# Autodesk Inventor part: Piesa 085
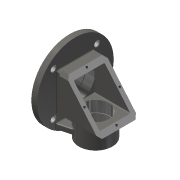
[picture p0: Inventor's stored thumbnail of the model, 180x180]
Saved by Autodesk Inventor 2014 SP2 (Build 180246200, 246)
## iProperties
Created: 2009-02
Part Number: Piesa 085
Document SubType Name: Modeling
Designer: Costel
Material: Steel, Cast
Density: 7.85 g/cm^3
Appearance: Steel - Cast
Mass: 4118.55 g
Surface Area: 1138.26 cm^2
Volume: 524.656 cm^3
Author: Costel
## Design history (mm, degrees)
sketch "Sketch2"
  geometry: L1 (0, -8.7)-(0, 113.1) reference; L2 (35.2, 0)-(-9.6, 0) reference; L3 (0, 87)-(13, 87); L4 (13, 87)-(13, 46); L5 (13, 46)-(17, 46); L6 (17, 46)-(32, 40.54); L7 (32, 40.54)-(32, 0); L8 (32, 0)-(0, 0); L9 (0, 0)-(0, 87)
  constraints: 14 end point, 4 point on line, 3 perpendicular, 2 parallel
  dimensions: "d1" = 174 diameter of L3 L2; "d2" = 92 diameter of L5 L2; "d3" = 20 deg angle of L5 L6; "d4" = 13 distance of L3.start L3.end; "d5" = 19 distance between parallel lines of L4 L7; "d6" = 4 distance of L4.end L5.end
revolve "Revolution1" sketch "Sketch2" stored, may be unused: angle "d7" = 90 deg
sketch "Sketch3"
  geometry: L1 (104.4, 0)-(-139.2, 0) reference; L2 (0, -104.4)-(0, 139.2) reference; L3 (-42.5, -42.5)-(42.5, -42.5); L4 (42.5, -42.5)-(42.5, 42.5); L5 (42.5, 42.5)-(-42.5, 42.5); L6 (-42.5, 42.5)-(-42.5, -42.5)
  constraints: 8 end point, 2 parallel, 2 perpendicular, 1 horizontal, 2 other
  dimensions: "d8" = 85 distance of L5.end L3.start
extrude "Extrusion1" join sketch "Sketch3" distance "d9" = 8; taper "d10" = 0 deg
sketch "Sketch4"
  geometry: L1 (-38, -45)-(38, -45); L2 (45, -38)-(45, 38); L3 (38, 45)-(-38, 45); L4 (-45, 38)-(-45, -38); L5 (0, -104.4)-(0, 139.2) reference; L6 (104.4, 0)-(-139.2, 0) reference; L7 (-45, -38)-(-38, -45); L8 (38, -45)-(45, -38); L9 (45, 38)-(38, 45); L10 (-38, 45)-(-45, 38); 4 further points
  constraints: 16 end point, 8 point on line, 2 parallel, 2 perpendicular, 1 horizontal, 2 other
  dimensions: "d11" = 90 distance of point (-45, 45) point (-45, -45); "d12" = 7 distance of L4.end point (-45, -45); "d13" = 7 distance of L1.start point (-45, -45) (= d12); "d14" = 7 distance of L1.end point (45, -45) (= d12); "d15" = 7 distance of L2.start point (45, -45) (= d14); "d16" = 7 distance of L2.end point (45, 45) (= d12); "d17" = 7 distance of L3.start point (45, 45) (= d16); "d18" = 7 distance of L3.end point (-45, 45) (= d12); "d19" = 7 distance of L4.start point (-45, 45) (= d18)
extrude "Extrusion2" join sketch "Sketch4" distance "d20" = 90.51897; taper "d21" = 0 deg
sketch "Sketch5"
  geometry: L1 (-45, -38)-(-45, 38) reference; L2 (-38, -45)-(-45, -38) reference; L3 (38, -45)-(-38, -45) reference; L4 (45, -38)-(38, -45) reference; L5 (45, 38)-(45, -38) reference; L6 (38, 45)-(45, 38) reference; L7 (-38, 45)-(38, 45) reference; L8 (-45, 38)-(-38, 45) reference; C1 r 87 at (0, 0) reference
extrude "Extrusion3" cut sketch "Sketch5" stored distance "d22" = 90.51897; taper "d23" = 0 deg
sketch "Sketch6"
  geometry: L1 (0, 7)-(90.519, 7) reference; L2 (-8, 49)-(-8, -125) reference; L3 (-53.052, -38)-(129.675, -38) reference; L4 (90.519, 0)-(90.519, 7) reference; L5 (0, -83)-(90.519, -83) reference; L6 (90.519, -83)-(90.519, -76) reference; L7 (90.519, -83)-(15, 7); L8 (15, 7)-(90.519, 7); L9 (90.519, 7)-(90.519, -83)
  constraints: 6 end point, 2 perpendicular, 1 point on line
  dimensions: "d24" = 23 distance from line of L2 L7.end
extrude "Extrusion4" cut sketch "Sketch6" distance "d25" = 90.51897; taper "d26" = 0 deg
sketch "Sketch7"
  geometry: L1 (0, -104.4)-(0, 139.2) reference; L2 (45.052, 0)-(-137.675, 0) reference; L3 (32, -40.54)-(32, 40.54) reference; L4 (13.65, 36)-(32, 36); L5 (32, 36)-(32, 0); L6 (11, 36)-(11, 37.5); L7 (11, 37.5)-(13.65, 37.5); L8 (13.65, 37.5)-(13.65, 36); L9 (32, 0)-(-8, 0); L10 (-8, 0)-(-8, 36); L11 (-8, 36)-(11, 36)
  constraints: 16 end point, 2 parallel, 1 collinear, 1 horizontal, 1 midpoint, 1 perpendicular
  dimensions: "d27" = 19 distance between parallel lines of L10 L6; "d28" = 2.65 distance of L6.end L7.end; "d29" = 40 distance between parallel lines of L10 L3; "d30" = 72 diameter of L4 L2; "d31" = 75 diameter of L7 L2
revolve "Revolution2" sketch "Sketch7" stored, may be unused: angle "d32" = 90 deg
sketch "Sketch8"
  geometry: L1 (-104.4, 0)-(139.2, 0) reference; L2 (35, 35)-(-35, 35); L3 (-35, 35)-(-35, -35); L4 (-35, -35)-(35, -35); L5 (35, -35)-(35, 35); L6 (0, -104.4)-(0, 139.2) reference
  constraints: 8 end point, 2 parallel, 2 perpendicular, 1 horizontal, 2 other
  dimensions: "d33" = 70 distance of L4.end L2.start
extrude "Extrusion5" cut sketch "Sketch8" stored distance "d34" = 90.51897; taper "d35" = 0 deg
fillet "Fillet3" dims "d102" = 2
fillet "Fillet4" dims "d103" = 2
sketch "Sketch9"
  geometry: L1 (45.052, 0)-(-137.675, 0) reference; L2 (0, -104.4)-(0, 139.2) reference; L3 (-46, 0)-(-46, -86); L4 (-8, -45)-(-98.519, -45) reference; L5 (-46, -86)-(-84, -86); L6 (-84, -86)-(-84, -45); L7 (-84, -45)-(-46, -45); L8 (-46, -45)-(-46, -86)
  constraints: 10 end point, 3 parallel, 2 point on line, 1 collinear, 1 horizontal, 1 perpendicular
  dimensions: "d36" = 46 distance between parallel lines of L2 L3; "d37" = 86 distance from line of L1 L3.end; "d38" = 76 diameter of L6 L3
revolve "Revolution3" sketch "Sketch9" stored, may be unused: angle "d39" = 90 deg
sketch "Sketch10"
  geometry: L1 (0, -118.76)-(0, 222.28) reference; L2 (63.325, 0)-(-192.493, 0) reference; L3 (-8, -35)-(-90.128, -35) reference; L4 (-8, -86)-(-84, -86) reference; L5 (-46, 0)-(-46, -86); L6 (-46, -86)-(-77, -86); L7 (-77, -35)-(-46, -35); L8 (-46, -35)-(-46, -86); L9 (-77, -58.7)-(-78.5, -58.7); L10 (-78.5, -58.7)-(-78.5, -60.85); L11 (-78.5, -60.85)-(-77, -60.85); L12 (-77, -78.85)-(-78.5, -78.85); L13 (-78.5, -78.85)-(-78.5, -81); L14 (-78.5, -81)-(-77, -81); L15 (-77, -58.7)-(-77, -35); L16 (-77, -86)-(-77, -81); L17 (-77, -78.85)-(-77, -60.85)
  constraints: 26 end point, 12 perpendicular, 6 parallel, 3 collinear, 2 point on line, 1 horizontal, 1 midpoint
  dimensions: "d58" = 62 diameter of L16 L5; "d59" = 65 diameter of L13 L5; "d60" = 2.15 distance of L12.end L13.end; "d61" = 2.15 distance of L9.end L10.end (= d60); "d62" = 5 distance of L6.end L14.end; "d63" = 18 distance of L12.start L11.end
revolve "Revolution4" sketch "Sketch10" stored, may be unused: angle "d64" = 90 deg
chamfer "Chamfer1" distance "d65" = 1; stored, may be unused: second distance "d66" = 2, angle "d67" = 45 deg
sketch "Sketch11"
  geometry: L1 (42.5, 40.5)-(42.5, -40.5) reference; L2 (42.5, -15)-(83, -15); L3 (83, -15)-(83, 15); L4 (83, 15)-(42.5, 15); L5 (42.5, 15)-(42.5, -15); L6 (104.4, 0)-(-139.2, 0) reference; C1 r 87 at (0, 0) reference
  constraints: 8 end point, 2 parallel, 1 horizontal, 1 perpendicular, 1 point on line, 1 other
  dimensions: "d69" = 83 distance from line of C1.centre L3; "d70" = 30 distance between parallel lines of L4 L2
extrude "Extrusion6" join sketch "Sketch11" stored distance "d71" = 90.51897; taper "d72" = 0 deg
sketch "Sketch12"
  geometry: L1 (0, 0)-(49.497, 49.497); L2 (-104.4, 0)-(139.2, 0) reference; C1 r 87 at (0, 0) reference; 1 further point
  constraints: 2 end point, 1 coincident
  dimensions: "d73" = 45 deg angle of L2 L1; "d74" = 70 distance of L1.start L1.end
hole "Hole1" sketch "Sketch12" at (49.497, 49.497) diameter "d75" = 11; stored, may be unused: countersink angle "d79" = 90 deg, drill point angle "d81" = 118 deg; dims "d76" = 6, "d77" = 25, "d78" = 5, "d80" = 8
fillet "Fillet1" dims "d85" = 2
chamfer "Chamfer2" distance "d86" = 1; stored, may be unused: second distance "d87" = 2, angle "d88" = 45 deg
pattern_circular "Circular Pattern2" dims "d90" = 360 deg
fillet "Fillet2" dims "d92" = 0.5
workplane "Work Plane1"
sketch "Sketch13"
  geometry: L1 (0, -45)-(33.726, -35.963); L2 (0, 0)-(46, 0)
  constraints: 4 end point, 1 horizontal, 2 other
  dimensions: "d94" = 45 distance of L2.start L1.start; "d95" = 15 deg angle of L2 L1
feature "Rib1" sketch "Sketch13" dims "d96" = 1, "d97" = 12, "d98" = 0, "d99" = 0, "d100" = 1, "d101" = 1
mirror "Mirror1"
fillet "Fillet7" dims "d106" = 0.5
fillet "Fillet8" dims "d107" = 2
fillet "Fillet9" dims "d108" = 2
fillet "Fillet10" dims "d109" = 2
fillet "Fillet11" dims "d110" = 2
fillet "Fillet12" dims "d111" = 2
fillet "Fillet13" dims "d112" = 2
fillet "Fillet14" dims "d113" = 2
sketch "Sketch14"
  geometry: L1 (-13.054, 71)-(-13.054, 5) reference; L2 (-15.665, 3)-(-101.822, 3) reference; L3 (-101.822, 73)-(-15.665, 73) reference; L4 (-58.743, 73)-(-58.743, 3); L5 (-13.054, 43.635)-(-13.054, 32.365); L6 (0, 76)-(0, 0) reference; A1 r 7.743 centre (-7.743, 38) between (-13.054, 32.365) and (-13.054, 43.635); 2 further points
  constraints: 4 end point, 3 midpoint, 2 point on circle, 2 point on line, 1 centre point, 1 collinear, 1 horizontal alignment, 1 tangent
  dimensions: "d115" = 51 distance from line of A1.centre L4
extrude "Extrusion7" join sketch "Sketch14" stored distance "d116" = 76; taper "d117" = 0 deg
sketch "Sketch15"
  geometry: L1 (-13.054, 71)-(-13.054, 5) reference; L2 (-101.822, 73)-(-15.665, 73); L3 (-9.138, -7)-(-108.349, -7) reference; L4 (-58.487, 78)-(-58.487, -2); L5 (-117.487, 0)-(-117.487, 76) reference; 6 further points
  constraints: 4 end point, 3 horizontal alignment, 3 midpoint, 1 perpendicular, 1 vertical alignment
  dimensions: "d119" = 105 distance of point (-7.487, 38) point (-112.487, 38); "d120" = 54 horizontal distance of L4.start point (-112.487, 38); "d121" = 80 distance of L4.end L4.start; "d138" = 5 distance from line of point (-112.487, 38) L5
hole "Hole2" sketch "Sketch15" at (-58.487, 78), (-112.487, 38), (-58.487, -2), (-7.487, 38) diameter "d122" = 4.917; stored, may be unused: countersink angle "d126" = 90 deg, drill point angle "d128" = 118 deg; dims "d123" = 13, "d124" = 4, "d125" = 2, "d127" = 14
hole "Hole3" diameter "d131" = 4.917; stored, may be unused: countersink angle "d135" = 90 deg, drill point angle "d137" = 118 deg; dims "d129" = 10, "d130" = 10, "d132" = 10, "d133" = 4, "d134" = 2, "d136" = 14
body "Solid1"
node "Projected Loop1"
other parameters: "d42" = 62
